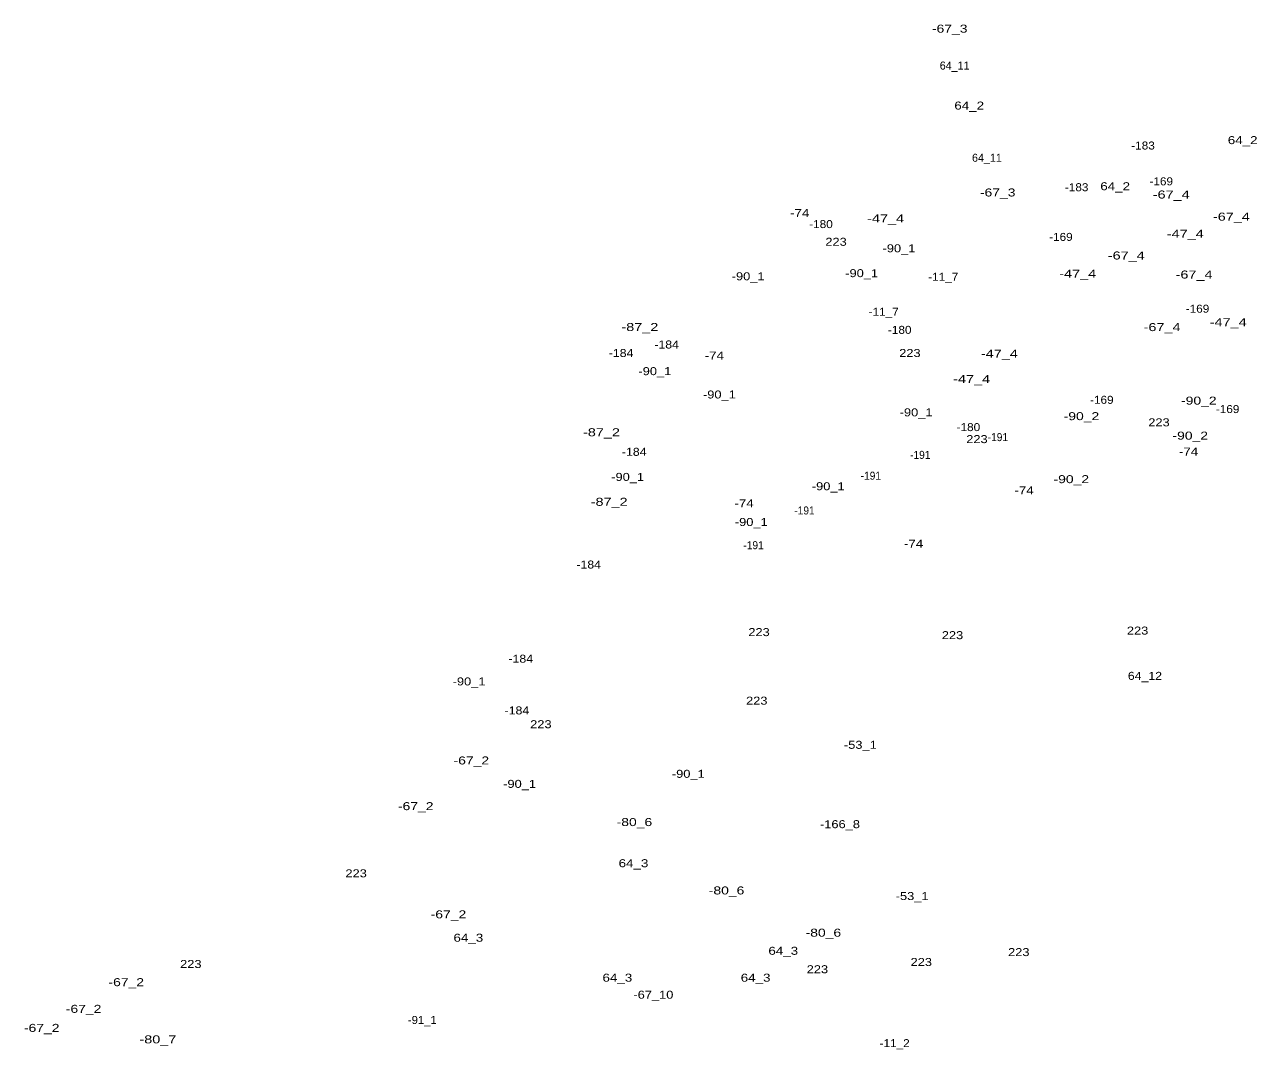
# Model space of a CAD drawing. Extents: x -662996 to -659766, y -998554 to -993949.
# Drawn here: x -662448 to -661835, y -995240 to -994727 of the extents above; entities that cross this region are included whole.
import ezdxf
from ezdxf.enums import TextEntityAlignment as Align

# ---------------------------------------------------------------- set-up
doc = ezdxf.new("R2010")
doc.units = 0
doc.header["$LTSCALE"] = 1.6
doc.layers.add('24', color=7, linetype='Continuous')

msp = doc.modelspace()

# ---------------------------------------------------------------- texts
at = {"layer": '24'}
for s, width, p in [('-67_3', 1.3, (-661985.481, -994731.38)), ('64_2', 1.25, (-661975.73, -994769.84)), ('64_2', 1.25, (-661839.02, -994787.12)), ('-183', 1.1, (-661888.831, -994789.81)), ('-183', 1.1, (-661922.01, -994810.66)), ('64_2', 1.25, (-661902.77, -994810.17)), ('-169', 1.1, (-661879.72, -994807.72)), ('-67_3', 1.3, (-661961.49, -994813.29)), ('-67_4', 1.35, (-661874.731, -994814.33)), ('-74', 1.25, (-662060.5, -994823.57)), ('-180', 1.1, (-662049.831, -994829.09)), ('-47_4', 1.35, (-662017.52, -994826.28)), ('-67_4', 1.35, (-661844.65, -994825.38)), ('-169', 1.1, (-661929.89, -994835.51)), ('-47_4', 1.35, (-661867.709, -994833.96)), ('223', 1.2, (-662042.309, -994837.94)), ('-90_1', 1.2, (-662010.841, -994841.2)), ('-67_4', 1.35, (-661897.201, -994844.81)), ('-90_1', 1.2, (-662029.5, -994853.64)), ('-47_4', 1.35, (-661921.48, -994853.94)), ('-67_4', 1.35, (-661863.311, -994854.33)), ('-90_1', 1.2, (-662086.25, -994855.2)), ('-11_7', 1.1, (-661988.731, -994855.47)), ('-11_7', 1.1, (-662018.49, -994872.95)), ('-169', 1.1, (-661861.59, -994871.41)), ('-47_4', 1.35, (-661846.25, -994878.14)), ('-87_2', 1.35, (-662140.39, -994880.56)), ('-180', 1.1, (-662010.471, -994881.98)), ('-67_4', 1.35, (-661879.301, -994880.62)), ('-184', 1.15, (-662127.01, -994889.31)), ('-184', 1.15, (-662149.77, -994893.56)), ('-74', 1.25, (-662103.15, -994894.81)), ('223', 1.2, (-662005.38, -994893.56)), ('-47_4', 1.35, (-661960.64, -994893.89)), ('-90_1', 1.2, (-662132.89, -994902.63)), ('-47_4', 1.35, (-661974.51, -994906.57)), ('-90_1', 1.2, (-662100.63, -994914.3)), ('-169', 1.1, (-661909.429, -994916.96)), ('-90_2', 1.3, (-661860.94, -994917.37)), ('-169', 1.1, (-661846.54, -994921.59)), ('-90_1', 1.2, (-662002.291, -994923.24)), ('-90_2', 1.3, (-661919.63, -994925.14)), ('223', 1.2, (-661880.85, -994928.23)), ('-87_2', 1.35, (-662159.58, -994933.18)), ('-180', 1.1, (-661976.13, -994930.61)), ('223', 1.2, (-661971.86, -994936.61)), ('-191', 0.95, (-661961.4, -994935.61)), ('-90_2', 1.3, (-661865.22, -994934.87)), ('-184', 1.15, (-662143.21, -994942.97)), ('-191', 0.95, (-662000.21, -994944.49)), ('-74', 1.25, (-661866.051, -994942.81)), ('-90_1', 1.2, (-662146.49, -994955.51)), ('-191', 0.95, (-662024.91, -994954.91)), ('-90_2', 1.3, (-661924.69, -994956.64)), ('-90_1', 1.2, (-662046.211, -994960.18)), ('-74', 1.25, (-661948.311, -994962.24)), ('-87_2', 1.35, (-662155.74, -994967.96)), ('-74', 1.25, (-662088.301, -994968.71)), ('-191', 0.95, (-662058.09, -994972.28)), ('-90_1', 1.2, (-662084.691, -994978.06)), ('-191', 0.95, (-662083.56, -994989.65)), ('-74', 1.25, (-662003.53, -994988.9)), ('-184', 1.15, (-662165.98, -994999.32)), ('223', 1.2, (-661891.54, -995032.35)), ('223', 1.2, (-662080.809, -995033.11)), ('223', 1.2, (-661984.079, -995034.64)), ('-184', 1.15, (-662199.93, -995046.41)), ('64_12', 1.15, (-661887.87, -995054.99)), ('-90_1', 1.2, (-662225.78, -995057.77)), ('223', 1.2, (-662081.949, -995067.4)), ('-184', 1.15, (-662201.86, -995072.28)), ('223', 1.2, (-662189.87, -995079.17)), ('-53_1', 1.2, (-662030.16, -995089.47)), ('-67_2', 1.3, (-662224.65, -995097.29)), ('-90_1', 1.2, (-662116.181, -995103.97)), ('-90_1', 1.2, (-662200.52, -995109)), ('-67_2', 1.3, (-662252.451, -995120.14)), ('-80_6', 1.3, (-662143.12, -995128.09)), ('-166_8', 1.2, (-662040.34, -995129.15)), ('64_3', 1.25, (-662143.579, -995148.67)), ('223', 1.2, (-662282.25, -995153.73)), ('-80_6', 1.3, (-662097.04, -995162.28)), ('-53_1', 1.2, (-662004.26, -995165.09)), ('-67_2', 1.3, (-662236.081, -995174.24)), ('64_3', 1.25, (-662226.14, -995185.93)), ('-80_6', 1.3, (-662048.65, -995183.41)), ('64_3', 1.25, (-662068.699, -995192.46)), ('223', 1.2, (-661999.689, -995198.06)), ('223', 1.2, (-661950.949, -995193.11)), ('223', 1.2, (-662364.89, -995199.06)), ('223', 1.2, (-662051.63, -995201.68)), ('-67_2', 1.3, (-662397.171, -995208.15)), ('64_3', 1.25, (-662151.64, -995205.91)), ('64_3', 1.25, (-662082.52, -995205.91)), ('-67_10', 1.2, (-662133.63, -995214.42)), ('-67_2', 1.3, (-662418.5, -995221.49)), ('-91_1', 1.05, (-662249.181, -995227.05)), ('-67_2', 1.3, (-662439.441, -995231.01)), ('-80_7', 1.35, (-662381.36, -995236.74)), ('-11_2', 1.1, (-662013, -995238.64))]:
    msp.add_text(s, height=4, dxfattribs=dict(at, width=width)).set_placement(p, align=Align.CENTER)
for p in [(-661983.02, -994749.84), (-661966.89, -994795.94)]:
    msp.add_text('64_11', height=4, dxfattribs=at).set_placement(p, align=Align.CENTER)

doc.saveas('drawing.dxf')
